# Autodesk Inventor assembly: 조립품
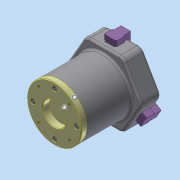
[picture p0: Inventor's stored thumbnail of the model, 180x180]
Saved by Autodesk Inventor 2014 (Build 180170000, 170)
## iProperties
Created: 2023-07
Part Number: 조립품
Document SubType Name: Assembly
Designer: dg
Author: dg
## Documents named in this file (13)
- C:\Users\dg\Desktop\630706V1008\조립품.iam
- C:\Users\dg\Desktop\630706V1008\본체.ipt
- C:\Users\dg\Desktop\630706V1008\척.ipt
- C:\Users\dg\Desktop\630706V1008\O링 P16.ipt
- C:\Users\dg\Desktop\630706V1008\커버.ipt
- C:\Users\dg\Desktop\630706V1008\O링 P44.ipt
- C:\Users\dg\Desktop\630706V1008\볼트 M8 x 20.ipt
- C:\Users\dg\Desktop\630706V1008\피스톤.ipt
- C:\Users\dg\Desktop\630706V1008\가변스프링.ipt
- C:\Users\dg\Desktop\630706V1008\피스톤 로드.ipt
- C:\Users\dg\Desktop\630706V1008\앤드캡.ipt
- C:\Users\dg\Desktop\630706V1008\볼트 M3 x 6.ipt
- C:\Users\dg\Desktop\630706V1008\볼트 M4 x 10.ipt
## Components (7 placed, 5 different names)
1. O링 P44:1 — 플러쉬:1
2. O링 P44:2 — 플러쉬:2
3. 피스톤:1 — 플러쉬:2
4. O링 P16:2 — 플러쉬:3
5. 가변스프링:1
6. 피스톤 로드:1
7. O링 P16:3
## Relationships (3: Flush 3)
- 플러쉬:1 [Flush]: O링 P44:1
- 플러쉬:2 [Flush]: O링 P44:2 ↔ 피스톤:1
- 플러쉬:3 [Flush]: O링 P16:2
